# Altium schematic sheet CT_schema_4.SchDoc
size 298 x 247 mm
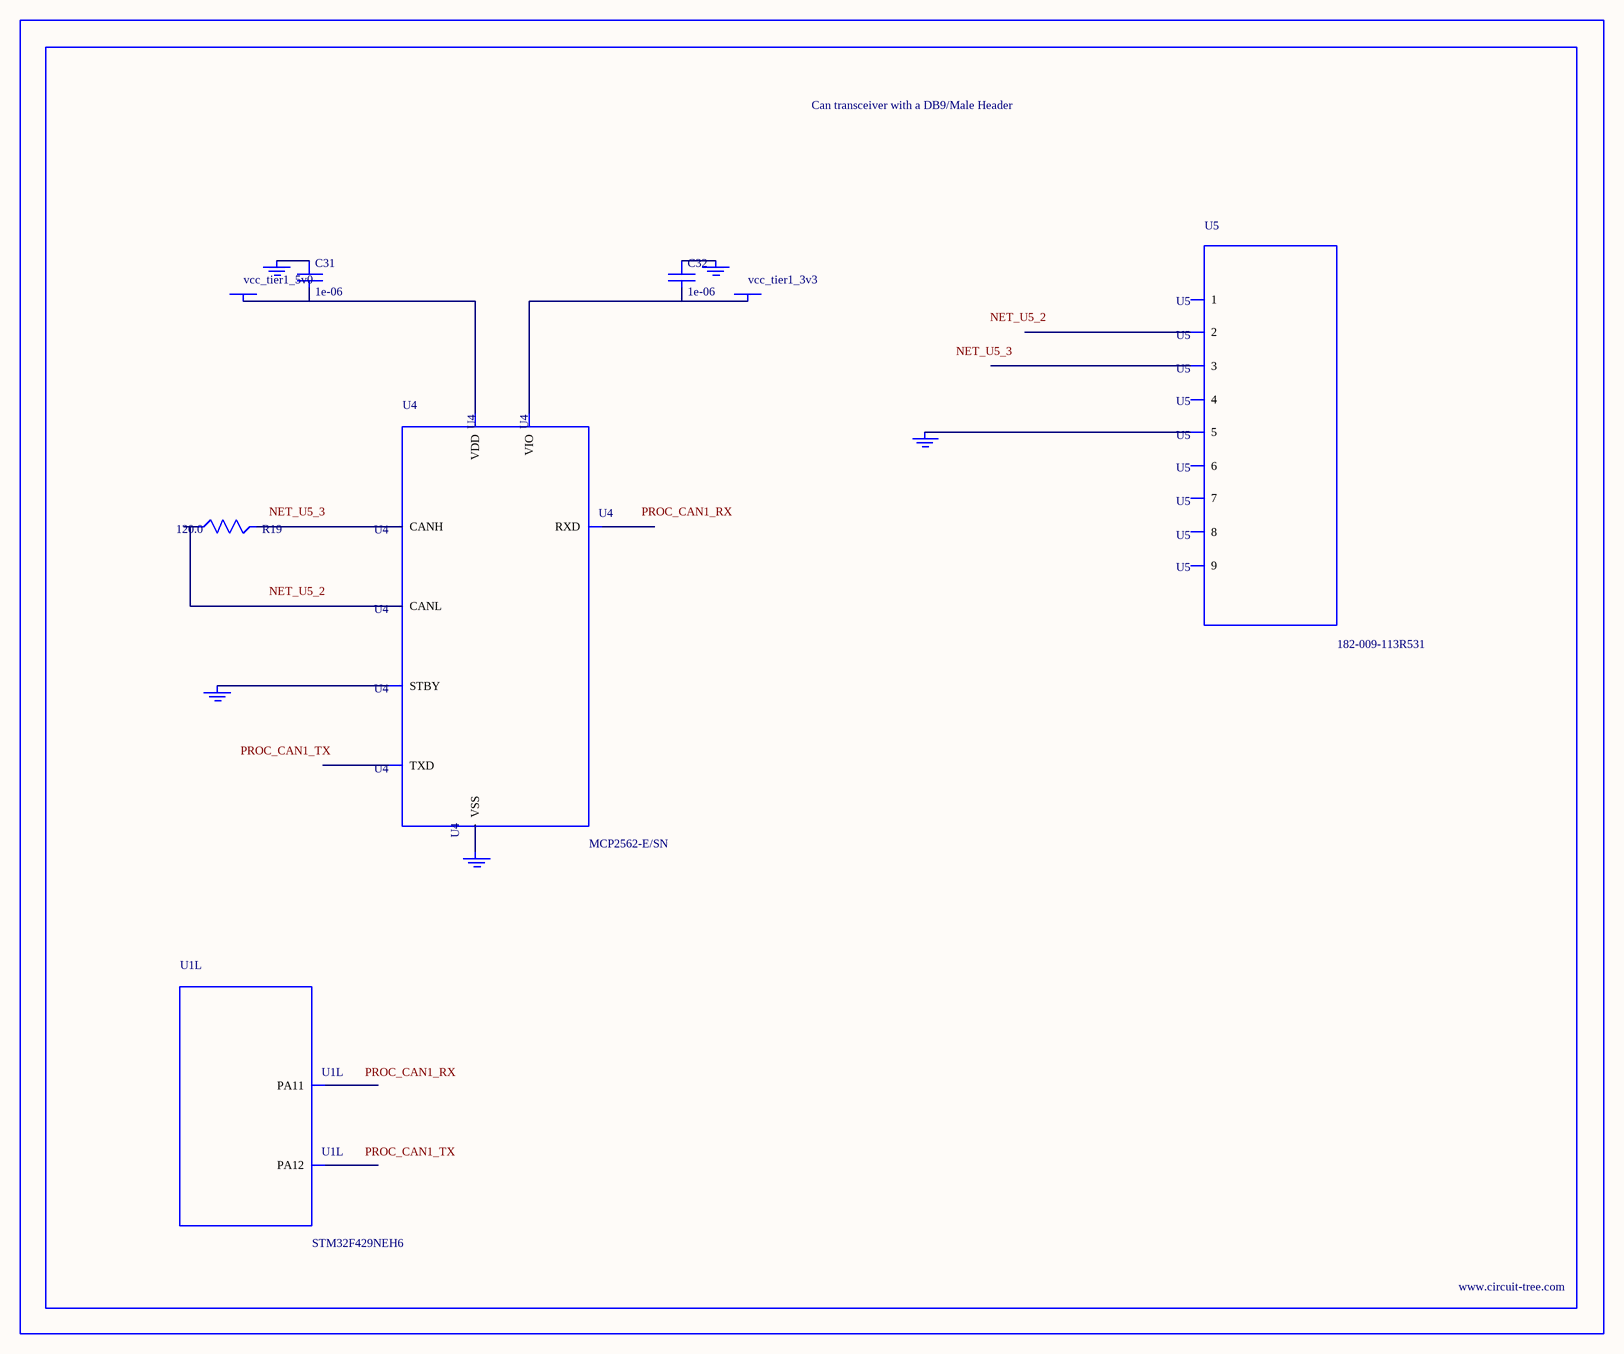
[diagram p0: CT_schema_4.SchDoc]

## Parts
BORDER3  (no value)
C31  1e-06  [C0603]
C32  1e-06  [C0603]
GND_INSTANCE_3_0  (no value)
GND_INSTANCE_3_1  (no value)
GND_INSTANCE_3_2  (no value)
GND_INSTANCE_3_3  (no value)
GND_INSTANCE_3_4  (no value)
POWER_INSTANCE_3_0  vcc_tier1_5v0
POWER_INSTANCE_3_1  vcc_tier1_3v3
R19  120.0  [R0603]
U1  STM32F429NEH6  [TFBGA216]  (part L of 17)
U4  MCP2562-E/SN  [SOIC-8]
U5  182-009-113R531  [182-009-MALE]

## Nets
NetC31_1: C31.1 GND_INSTANCE_3_0.0(GND)
NetC31_2: C31.2 POWER_INSTANCE_3_0.0(PWR) U4.3(VDD)
NetC32_1: C32.1 GND_INSTANCE_3_1.0(GND)
NetC32_2: C32.2 POWER_INSTANCE_3_1.0(PWR) U4.5(VIO)
NetGND_INSTANCE_3_2_0: GND_INSTANCE_3_2.0(GND) U4.8(STBY)
NetGND_INSTANCE_3_3_0: GND_INSTANCE_3_3.0(GND) U4.2(VSS)
NetGND_INSTANCE_3_4_0: GND_INSTANCE_3_4.0(GND) U5.5
NetR19_1: R19.1 U4.6(CANL)
NetR19_2: R19.2 U4.7(CANH)

Not connected (* = marked no-connect by the designer): U1 B15(PA12) C15(PA11); U4 1(TXD) 4(RXD); U5 1 2 3 4 6 7 8 9

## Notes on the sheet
- Labels drawn without touching a wire or pin: NET_U5_2, NET_U5_3, PROC_CAN1_RX, PROC_CAN1_TX

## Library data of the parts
BORDER3 = BORDER_PAGE3
C31 C32 = C0603C105K3RACTU
GND_INSTANCE_3_0-GND_INSTANCE_3_4 = GND
POWER_INSTANCE_3_0 POWER_INSTANCE_3_1 = PWR
R19 = RC0603JR-07120RL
